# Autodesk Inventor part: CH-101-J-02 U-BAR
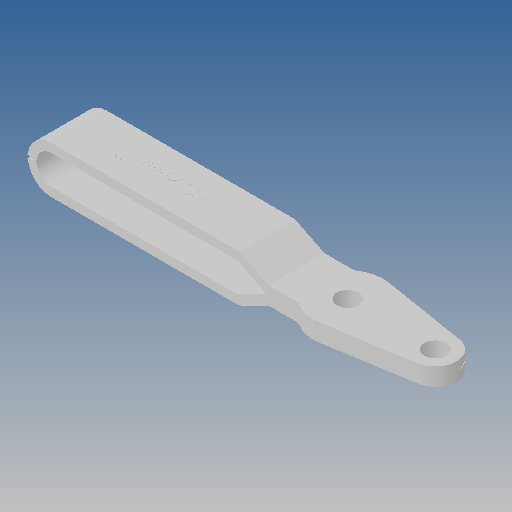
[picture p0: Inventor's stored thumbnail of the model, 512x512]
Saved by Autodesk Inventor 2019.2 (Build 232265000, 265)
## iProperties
Created: 2012-09
Part Number: CH-101-J-02 U-BAR
Material: Ogólny
Document SubType Name: Modeling
Designer: CADENGINEERING4
Density: 1 g/cm^3
Appearance: Domyślna
Author: CADENGINEERING4
Revision Number: ÈÎºÎ
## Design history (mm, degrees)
feature "ÇÐ³ý-À­Éì2"
feature "ÇÐ³ý-À­Éì5"
node "Bryła1"
node "Bryła2"
